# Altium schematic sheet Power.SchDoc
size A4; SheetNumber: 1; SheetTotal: 2
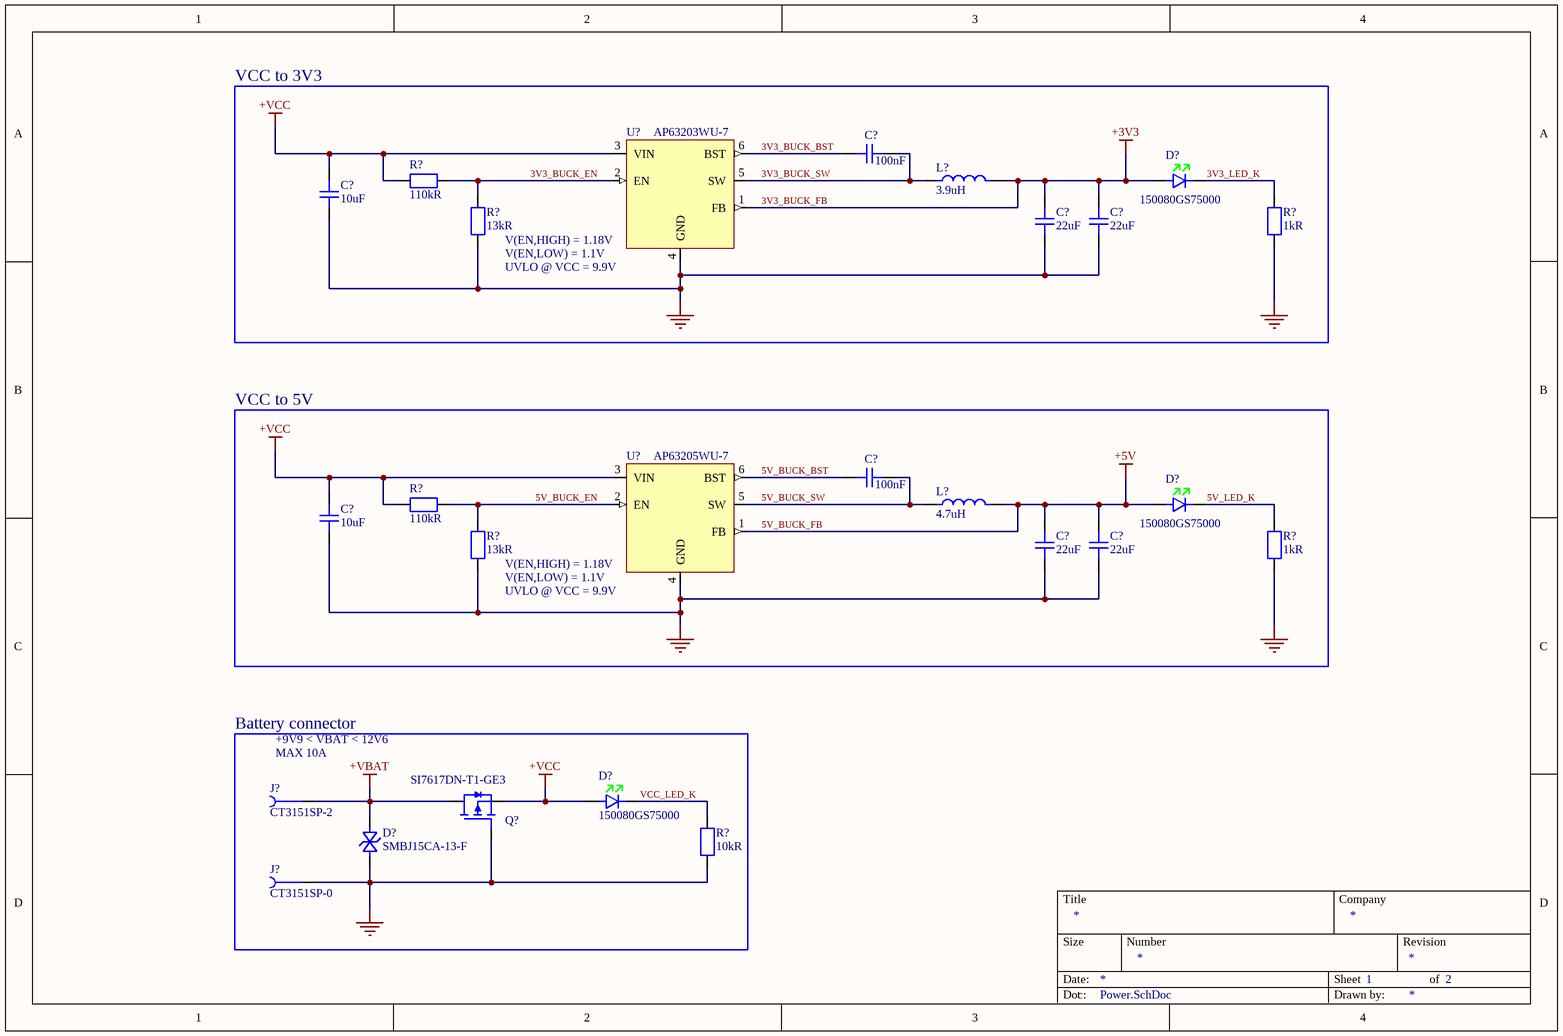
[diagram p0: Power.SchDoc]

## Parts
(Parts that share a designator on the sheet are numbered #1, #2 ... from top to bottom, then left to right.)
C?#1  value 100nF  [C_Yageo_CC_0402_A]  (hidden comment: CC0402MRX5R6BB104)
C?#2  value 10uF  [C_Yageo_CC_0805_A]  (hidden comment: CC0805KRX5R7BB106)
C?#3  value 22uF  [C_Yageo_CC_0805_A]  (hidden comment: CC0805MKX5R6BB226)
C?#4  value 22uF  [C_Yageo_CC_0805_A]  (hidden comment: CC0805MKX5R6BB226)
C?#5  value 100nF  [C_Yageo_CC_0402_A]  (hidden comment: CC0402MRX5R6BB104)
C?#6  value 10uF  [C_Yageo_CC_0805_A]  (hidden comment: CC0805KRX5R7BB106)
C?#7  value 22uF  [C_Yageo_CC_0805_A]  (hidden comment: CC0805MKX5R6BB226)
C?#8  value 22uF  [C_Yageo_CC_0805_A]  (hidden comment: CC0805MKX5R6BB226)
D?#1  150080GS75000  [D_LED_We_150080GS75000]
D?#2  150080GS75000  [D_LED_We_150080GS75000]
D?#3  150080GS75000  [D_LED_We_150080GS75000]
D?#4  SMBJ15CA-13-F  [D_TVS_BI_Diodes_SMBJ15CA-13-F_A]
J?#1  CT3151SP-2  [J_CalTest_CT3151SP-2]
J?#2  CT3151SP-0  [J_CalTest_CT3151SP-0]
L?#1  value 3.9uH  [L_Murata_1255AY-XXXX=P3]  (hidden comment: 1255AY-3R9N=P3)
L?#2  value 4.7uH  [L_Murata_1255AY-XXXX=P3]  (hidden comment: 1255AY-4R7M=P3)
Q?  SI7617DN-T1-GE3  [Q_Vishay_SI7617DN-T1-GE3]
R?#1  value 110kR  [R_Yageo_RCL_0402_A]  (hidden comment: RC0402FR-07110KL)
R?#2  value 13kR  [R_Yageo_RCL_0402_A]  (hidden comment: RC0402FR-0713KL)
R?#3  value 1kR  [R_Yageo_RCL_0402_A]  (hidden comment: RC0402FR-071KL)
R?#4  value 110kR  [R_Yageo_RCL_0402_A]  (hidden comment: RC0402FR-07110KL)
R?#5  value 13kR  [R_Yageo_RCL_0402_A]  (hidden comment: RC0402FR-0713KL)
R?#6  value 1kR  [R_Yageo_RCL_0402_A]  (hidden comment: RC0402FR-071KL)
R?#7  value 10kR  [R_Yageo_RCL_0402_A]  (hidden comment: RC0402FR-0710KL)
U?#1  AP63203WU-7  [U_Diodes_AP623xx]
U?#2  AP63205WU-7  [U_Diodes_AP623xx]

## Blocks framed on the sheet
VCC to 3V3: C?#1-C?#4 D?#1 L?#1 R?#1-R?#3 U?#1
VCC to 5V: C?#5-C?#8 D?#2 L?#2 R?#4-R?#6 U?#2
Battery connector: D?#3 D?#4 J?#1 J?#2 Q? R?#7

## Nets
3V3_BUCK_FB: C?#3.2 C?#4.2 D?#1.1 L?#1.2 U?#1.1(FB)  [also labelled +3V3]
5V_BUCK_FB: C?#7.2 C?#8.2 D?#2.1 L?#2.2 U?#2.1(FB)  [also labelled +5V]
+VBAT: D?#4.1 J?#1.1 Q?.1(D)
+VCC: C?#2.2 C?#6.2 D?#3.1 Q?.3(S) R?#1.2 R?#4.2 U?#1.3(VIN) U?#2.3(VIN)
GND: C?#2.1 C?#3.1 C?#4.1 C?#6.1 C?#7.1 C?#8.1 D?#4.2 J?#2.1 Q?.2(G) R?#2.1 R?#3.1 R?#5.1 R?#6.1 R?#7.1 U?#1.4(GND) U?#2.4(GND)
3V3_BUCK_BST: C?#1.2 U?#1.6(BST)
3V3_BUCK_EN: R?#1.1 R?#2.2 U?#1.2(EN)
3V3_BUCK_SW: C?#1.1 L?#1.1 U?#1.5(SW)
3V3_LED_K: D?#1.2 R?#3.2
5V_BUCK_BST: C?#5.2 U?#2.6(BST)
5V_BUCK_EN: R?#4.1 R?#5.2 U?#2.2(EN)
5V_BUCK_SW: C?#5.1 L?#2.1 U?#2.5(SW)
5V_LED_K: D?#2.2 R?#6.2
VCC_LED_K: D?#3.2 R?#7.2

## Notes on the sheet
- (near U?#1) V(EN,HIGH) = 1.18V
- V(EN,LOW) = 1.1V
- (near U?#1) UVLO @ VCC = 9.9V
- (near U?#2) V(EN,HIGH) = 1.18V
- (near U?#2) UVLO @ VCC = 9.9V
- +9V9 < VBAT < 12V6
- (near J?#1) MAX 10A

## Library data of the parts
C?#1 C?#5 = CMP-001-00009-8: Multilayer Ceramic Capacitor, 0.1 uF, 25 V, ± 20%, X7R, 0402 [1005 Metric]; Dielectric: X5R; Temperature Coefficient: 30ppm/°C; Voltage Rating: 10V
C?#2 C?#6 = CMP-001-00018-3: 0805 10 uF 16 V ±10% Tolerance X5R Multilayer Ceramic Chip Capacitor; Voltage Rating (DC): 16V
C?#3 C?#4 C?#7 C?#8 = CMP-001-00014-5: Multilayer Ceramic Capacitor, 22 uF, 10 V, ± 20%, X5R, 0805 [2012 Metric]; Voltage Rating (DC): 10V
D?#1 D?#2 = CMP-007-00000-6: WURTH ELEKTRONIK - 150080GS75000 - LED, Green, SMD, 0805, 30 mA, 3.2 V, 520 nm; Forward Current: 30mA; Forward Voltage: 3.2V; Luminous Intensity: 450mcd; Max Reverse Voltage (DC): 5V; Lens Transparency: Clear; Power Dissipation: 105mW; Lens Style: Clear,Flat,Rectangular; Lens Size: 1.25mm; Viewing Angle: 140°; Test Current: 20mA; Dominant Wavelength: 520nm; Lens Color: Colorless
D?#3 = CMP-007-00000-6: WURTH ELEKTRONIK - 150080GS75000 - LED, Green, SMD, 0805, 30 mA, 3.2 V, 520 nm; Viewing Angle: 140°; Lens Transparency: Clear; Reverse Voltage: 5V; Lens Size: 1.25mm; Lens Color: Colorless; Lens Style: Clear,Flat,Rectangular; Power Dissipation: 105mW; Wavelength: 520nm; Forward Voltage: 3.2V; Test Current: 20mA; Forward Current: 30mA; Luminous Intensity: 450mcd
D?#4 = CMP-004-00000-8: Tvs Diode, Bidir, 15V, 600W, Do-214Aa Rohs Compliant: Yes; Max Reverse Leakage Current: 5uA; Reverse Breakdown Voltage: 16.7V; Breakdown Voltage: 19.2V; Clamping Voltage: 24.4V; Power Line Protection: No; Max Surge Current: 24A; Number of Bidirectional Channels: 1; Test Current: 1mA; Value: 280pF; Polarity: Bidirectional; Diode Type: ZENER
J?#1 = CMP-002-00001-9: Conn 4mm Safety Banana Jack F 1 POS Solder RA Thru-Hole 1 Port Bag; pin to pad: 1>1+2+3+4; Body Material: Nylon,Polyamide,PA66; Insulation: Mating End Insulated; Gender: Female
J?#2 = CMP-002-00000-11: Conn 4mm Safety Banana Jack F 1 POS Solder RA Thru-Hole 1 Port Bag; pin to pad: 1>1+2+3+4; Body Material: Nylon,Polyamide,PA66; Insulation: Mating End Insulated; Gender: Female
L?#1 = CMP-006-00002-2: Inductor Power Shielded Wirewound 3.9uH 30% 100KHz Ferrite 4.2A 0.0264Ohm DCR 2424 T/R; DC Resistance (DCR): 26.4mR; Saturation Current: 4.7A
L?#2 = CMP-006-00001-5: Inductor Power Shielded Wirewound 4.7uH 20% 100KHz Ferrite 4A 0.0276Ohm DCR 2424 T/R; DC Resistance (DCR): 27.6mR; Current Rating: 4.5A
Q? = CMP-00000-6: P CHANNEL MOSFET, -30V, 35A; Transistor; Transistor Polarity: P Channel; Continuous Drain Current Id: -35A; Source; pin to pad: 1>5+6+7+8 2>4 3>1+2+3; Rise Time: 43ns; Drain to Source Resistance: 12.3mR; Turn-Off Delay Time: 30ns; Turn-On Delay Time: 40ns; Threshold Voltage: -2.5V; Max Power Dissipation: 52W; Fall Time: 11ns; Power Dissipation: 3.7W; Polarity: P-CHANNEL; Number of Elements: 1; Input Capacitance: 1.8nF; Gate to Source Voltage (Vgs): 25V
R?#1 R?#4 = CMP-009-00000-7: SMD Chip Resistor, 110 kOhm, ± 1%, 63 mW, 0402 [1005 Metric], Thick Film, General Purpose; Max Power Dissipation: 63mW; Voltage Rating (DC): 50V; Temperature Coefficient: 100ppm/°C
R?#2 R?#5 = CMP-009-00001-7: SMD Chip Resistor, 13 kOhm, ± 1%, 63 mW, 0402 [1005 Metric], Thick Film, General Purpose; Temperature Coefficient: 100ppm/°C; Voltage Rating: 50V; Max Power Dissipation: 63mW; Power Rating: 62.5mW
R?#3 R?#6 = CMP-009-00002-7: SMD Chip Resistor, 1 kOhm, ± 1%, 62.5 mW, 0402 [1005 Metric], Thick Film, General Purpose; Temperature Coefficient: 100ppm/°C; Voltage Rating (AC): 50V; Power Rating: 62.5mW; Max Power Dissipation: 63mW
R?#7 = CMP-009-00003-7: SMD Chip Resistor, 10 kOhm, ± 1%, 62.5 mW, 0402 [1005 Metric], Thick Film, General Purpose; Power Rating: 62.5mW; Temperature Coefficient: 100ppm/°C; Max Power Dissipation: 63mW; Voltage Rating (DC): 50V
U?#1 = CMP-019-00004-6: AP63203 Series 3.3 V 2 A SMT Fixed Low IQ Synchronous Buck - TSOT-26; Max Duty Cycle: 100%; Output Voltage: 3.3V; Number of Outputs: 1; Max Supply Voltage: 32V; Switching Frequency: 1.1MHz; Min Supply Voltage: 3.8V; Nominal Supply Current: 22uA; Output Current: 2A
U?#2 = CMP-019-00003-6: AP63205 Series 32 V 2 A 1.1 MHz Synchronous Buck Converter -TSOT-26; Number of Outputs: 1; Max Duty Cycle: 100%; Output Current: 2A; Switching Frequency: 1.1MHz; Max Supply Voltage: 32V; Output Voltage: 5V; Nominal Supply Current: 22uA; Min Supply Voltage: 3.8V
